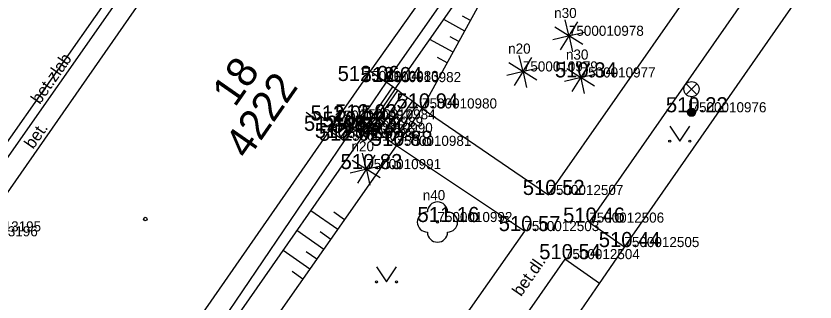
# Model space of a CAD drawing. Extents: x -669251 to -668549, y -1128351 to -1127698.
# Drawn here: x -668910.12 to -668870.46, y -1127865.22 to -1127851.02 of the extents above; entities that cross this region are included whole.
import ezdxf

# ---------------------------------------------------------------- set-up
doc = ezdxf.new("R2010")
doc.units = 0
for name, color, linetype in [('Vrstva 1', 7, 'Continuous'), ('Vrstva 10', 7, 'Continuous'), ('Vrstva 11', 7, 'Continuous'), ('Vrstva 14', 7, 'Continuous'), ('Vrstva 15', 7, 'Continuous'), ('Vrstva 2', 7, 'Continuous'), ('Vrstva 22', 7, 'Continuous'), ('Vrstva 24', 7, 'Continuous'), ('Vrstva 3', 7, 'Continuous'), ('Vrstva 33', 7, 'Continuous'), ('Vrstva 36', 7, 'Continuous'), ('Vrstva 40', 7, 'Continuous'), ('Vrstva 43', 7, 'Continuous'), ('Vrstva 44', 7, 'Continuous'), ('Vrstva 47', 7, 'Continuous'), ('Vrstva 5', 7, 'Continuous'), ('Vrstva 58', 7, 'Continuous'), ('Vrstva 6', 7, 'Continuous')]:
    doc.layers.add(name, color=color, linetype=linetype)

msp = doc.modelspace()

# ---------------------------------------------------------------- linework, layer by layer
at = {"layer": 'Vrstva 1'}
for p, q in [((-668882.677, -1127852.009), (-668882.677, -1127852.009)), ((-668884.962, -1127853.778), (-668884.962, -1127853.778)), ((-668892.859, -1127854.252), (-668892.859, -1127854.252)), ((-668891.745, -1127854.308), (-668891.745, -1127854.308)), ((-668882.094, -1127854.076), (-668882.094, -1127854.076)), ((-668889.962, -1127855.615), (-668889.962, -1127855.615)), ((-668876.589, -1127855.806), (-668876.589, -1127855.806)), ((-668894.225, -1127856.217), (-668894.225, -1127856.217)), ((-668893.009, -1127856.156), (-668893.009, -1127856.156)), ((-668894.554, -1127856.723), (-668894.554, -1127856.723)), ((-668893.631, -1127856.52), (-668893.631, -1127856.52)), ((-668894.015, -1127857.081), (-668894.015, -1127857.081)), ((-668893.154, -1127856.826), (-668893.154, -1127856.826)), ((-668893.808, -1127857.22), (-668893.808, -1127857.22)), ((-668891.237, -1127857.472), (-668891.237, -1127857.472)), ((-668892.737, -1127858.627), (-668892.737, -1127858.627)), ((-668883.69, -1127859.91), (-668883.69, -1127859.91)), ((-668889.2, -1127861.254), (-668889.2, -1127861.254)), ((-668881.667, -1127861.283), (-668881.667, -1127861.283)), ((-668884.887, -1127861.703), (-668884.887, -1127861.703)), ((-668879.919, -1127862.497), (-668879.919, -1127862.497)), ((-668882.875, -1127863.096), (-668882.875, -1127863.096))]:
    msp.add_line(p, q, dxfattribs=at)
at = {"layer": 'Vrstva 10'}
for p, q in [((-668883.69, -1127859.91), (-668874.225, -1127846.346)), ((-668881.667, -1127861.283), (-668872.238, -1127847.756)), ((-668891.745, -1127854.308), (-668887.822, -1127848.697)), ((-668891.293, -1127854.639), (-668887.343, -1127848.989)), ((-668879.919, -1127862.497), (-668870.46, -1127848.93)), ((-668913.476, -1127861.451), (-668905.08, -1127849.485)), ((-668913.109, -1127861.712), (-668904.712, -1127849.743)), ((-668891.293, -1127854.639), (-668892.563, -1127856.488)), ((-668889.962, -1127855.615), (-668883.69, -1127859.91)), ((-668901.53, -1127869.379), (-668892.563, -1127856.488)), ((-668901.884, -1127869.131), (-668893.808, -1127857.22)), ((-668884.887, -1127861.703), (-668891.237, -1127857.472)), ((-668879.919, -1127862.497), (-668881.667, -1127861.283)), ((-668884.887, -1127861.703), (-668893.875, -1127874.516)), ((-668881.164, -1127864.311), (-668879.919, -1127862.497)), ((-668882.875, -1127863.096), (-668891.824, -1127875.9)), ((-668881.164, -1127864.311), (-668882.875, -1127863.096)), ((-668889.953, -1127877.123), (-668881.164, -1127864.311))]:
    msp.add_line(p, q, dxfattribs=at)
at = {"layer": 'Vrstva 11'}
for p, q in [((-668892.516, -1127853.765), (-668891.745, -1127854.308)), ((-668891.745, -1127854.308), (-668893.009, -1127856.156)), ((-668891.414, -1127854.55), (-668891.745, -1127854.308)), ((-668892.683, -1127856.398), (-668891.414, -1127854.55)), ((-668892.442, -1127856.577), (-668891.172, -1127854.728)), ((-668891.293, -1127854.639), (-668891.414, -1127854.55)), ((-668891.172, -1127854.728), (-668891.293, -1127854.639)), ((-668890.93, -1127854.905), (-668891.172, -1127854.728)), ((-668892.201, -1127856.756), (-668890.93, -1127854.905)), ((-668891.96, -1127856.935), (-668890.688, -1127855.083)), ((-668890.688, -1127855.083), (-668890.93, -1127854.905)), ((-668890.446, -1127855.26), (-668890.688, -1127855.083)), ((-668891.719, -1127857.114), (-668890.446, -1127855.26)), ((-668891.478, -1127857.293), (-668890.204, -1127855.438)), ((-668891.237, -1127857.472), (-668889.962, -1127855.615)), ((-668890.204, -1127855.438), (-668890.446, -1127855.26)), ((-668889.962, -1127855.615), (-668890.204, -1127855.438)), ((-668893.808, -1127857.22), (-668893.009, -1127856.156)), ((-668893.009, -1127856.156), (-668892.683, -1127856.398)), ((-668892.683, -1127856.398), (-668892.563, -1127856.488)), ((-668894.554, -1127856.723), (-668894.015, -1127857.081)), ((-668892.563, -1127856.488), (-668892.442, -1127856.577)), ((-668892.442, -1127856.577), (-668892.201, -1127856.756)), ((-668892.201, -1127856.756), (-668891.96, -1127856.935)), ((-668894.015, -1127857.081), (-668893.808, -1127857.22)), ((-668891.96, -1127856.935), (-668891.719, -1127857.114)), ((-668891.719, -1127857.114), (-668891.478, -1127857.293)), ((-668891.478, -1127857.293), (-668891.237, -1127857.472))]:
    msp.add_line(p, q, dxfattribs=at)
at = {"layer": 'Vrstva 14'}
for p, q in [((-668889.962, -1127855.615), (-668886.276, -1127848.913)), ((-668900.226, -1127870.29), (-668891.237, -1127857.472))]:
    msp.add_line(p, q, dxfattribs=at)
at = {"layer": 'Vrstva 15'}
for p, q in [((-668887.848, -1127851.772), (-668888.889, -1127851.2)), ((-668887.559, -1127851.246), (-668887.953, -1127851.03)), ((-668888.137, -1127852.298), (-668888.576, -1127852.056)), ((-668888.427, -1127852.823), (-668889.58, -1127852.189)), ((-668888.716, -1127853.349), (-668889.2, -1127853.083)), ((-668894.153, -1127861.629), (-668895.488, -1127860.693)), ((-668893.808, -1127861.138), (-668894.343, -1127860.763)), ((-668894.842, -1127862.612), (-668896.173, -1127861.678)), ((-668894.497, -1127862.12), (-668895.03, -1127861.746)), ((-668895.531, -1127863.594), (-668896.858, -1127862.663)), ((-668895.186, -1127863.103), (-668895.718, -1127862.73)), ((-668895.875, -1127864.085), (-668896.405, -1127863.713))]:
    msp.add_line(p, q, dxfattribs=at)
at = {"layer": 'Vrstva 22'}
for p, q in [((-668882.685, -1127851.969), (-668882.857, -1127851.215)), ((-668882.711, -1127851.989), (-668883.367, -1127851.575)), ((-668882.243, -1127851.319), (-668882.657, -1127851.975)), ((-668883.471, -1127852.189), (-668882.717, -1127852.017)), ((-668882.697, -1127852.043), (-668883.111, -1127852.699)), ((-668882.669, -1127852.049), (-668882.497, -1127852.803)), ((-668881.987, -1127852.443), (-668882.643, -1127852.029)), ((-668882.637, -1127852.001), (-668881.883, -1127851.829)), ((-668884.97, -1127853.738), (-668885.142, -1127852.984)), ((-668884.528, -1127853.088), (-668884.942, -1127853.744)), ((-668884.996, -1127853.758), (-668885.652, -1127853.344)), ((-668884.922, -1127853.77), (-668884.168, -1127853.598)), ((-668882.128, -1127854.056), (-668882.784, -1127853.642)), ((-668882.102, -1127854.036), (-668882.274, -1127853.282)), ((-668881.66, -1127853.386), (-668882.074, -1127854.042)), ((-668885.756, -1127853.958), (-668885.002, -1127853.786)), ((-668884.982, -1127853.812), (-668885.396, -1127854.468)), ((-668884.954, -1127853.818), (-668884.782, -1127854.572)), ((-668884.272, -1127854.212), (-668884.928, -1127853.798)), ((-668882.054, -1127854.068), (-668881.3, -1127853.896)), ((-668882.888, -1127854.256), (-668882.134, -1127854.084)), ((-668882.114, -1127854.11), (-668882.528, -1127854.766)), ((-668882.086, -1127854.116), (-668881.914, -1127854.87)), ((-668881.404, -1127854.51), (-668882.06, -1127854.096)), ((-668892.745, -1127858.587), (-668892.917, -1127857.833)), ((-668892.303, -1127857.937), (-668892.717, -1127858.593)), ((-668892.771, -1127858.607), (-668893.427, -1127858.193)), ((-668893.531, -1127858.807), (-668892.777, -1127858.635)), ((-668892.757, -1127858.661), (-668893.171, -1127859.317)), ((-668892.729, -1127858.667), (-668892.557, -1127859.421)), ((-668892.047, -1127859.061), (-668892.703, -1127858.647)), ((-668892.697, -1127858.619), (-668891.943, -1127858.447))]:
    msp.add_line(p, q, dxfattribs=at)
for centre, radius in [((-668882.677, -1127852.009), 0.04), ((-668884.962, -1127853.778), 0.04), ((-668882.094, -1127854.076), 0.04), ((-668892.737, -1127858.627), 0.04), ((-668889.2, -1127861.254), 0.05)]:
    msp.add_circle(centre, radius, dxfattribs=at)
for centre, start, end in [((-668889.2, -1127860.754), 0, 180), ((-668889.7, -1127861.254), 90, 270), ((-668888.7, -1127861.254), 270, 90), ((-668889.2, -1127861.754), 180, 0)]:
    msp.add_arc(centre, 0.5, start, end, dxfattribs=at)
at = {"layer": 'Vrstva 24'}
for p, q in [((-668895.719, -1127855.806), (-668895.202, -1127856.16)), ((-668895.202, -1127856.16), (-668895.371, -1127855.742)), ((-668895.371, -1127855.742), (-668894.648, -1127856.236)), ((-668894.648, -1127856.236), (-668894.789, -1127856.007)), ((-668894.913, -1127856.188), (-668894.648, -1127856.236)), ((-668893.67, -1127856.578), (-668894.225, -1127856.217)), ((-668894.015, -1127857.081), (-668893.67, -1127856.578))]:
    msp.add_line(p, q, dxfattribs=at)
at = {"layer": 'Vrstva 33'}
for p, q in [((-668876.854, -1127854.391), (-668876.324, -1127854.921)), ((-668876.854, -1127854.921), (-668876.324, -1127854.391)), ((-668876.589, -1127855.806), (-668876.589, -1127855.031))]:
    msp.add_line(p, q, dxfattribs=at)
for centre, radius in [((-668876.589, -1127854.656), 0.375), ((-668876.589, -1127855.806), 0.2), ((-668876.589, -1127855.806), 0.18), ((-668876.589, -1127855.806), 0.16), ((-668876.589, -1127855.806), 0.14), ((-668876.589, -1127855.806), 0.12), ((-668876.589, -1127855.806), 0.1), ((-668876.589, -1127855.806), 0.08), ((-668876.589, -1127855.806), 0.06), ((-668876.589, -1127855.806), 0.04), ((-668876.589, -1127855.806), 0.02)]:
    msp.add_circle(centre, radius, dxfattribs=at)
at = {"layer": 'Vrstva 36'}
for p, q in [((-668877.673, -1127856.494), (-668877.173, -1127857.244)), ((-668877.173, -1127857.244), (-668876.673, -1127856.494)), ((-668892.232, -1127863.479), (-668891.732, -1127864.229)), ((-668891.732, -1127864.229), (-668891.232, -1127863.479))]:
    msp.add_line(p, q, dxfattribs=at)
for centre in [(-668877.673, -1127857.244), (-668876.673, -1127857.244), (-668892.232, -1127864.229), (-668891.232, -1127864.229)]:
    msp.add_circle(centre, 0.05, dxfattribs=at)
at = {"layer": 'Vrstva 5'}
for p, q in [((-668892.516, -1127853.765), (-668888.214, -1127847.662)), ((-668912.114, -1127862.052), (-668903.875, -1127850.202)), ((-668892.859, -1127854.252), (-668892.516, -1127853.765)), ((-668894.554, -1127856.723), (-668894.225, -1127856.217)), ((-668902.765, -1127868.518), (-668894.554, -1127856.723))]:
    msp.add_line(p, q, dxfattribs=at)
at = {"layer": 'Vrstva 58'}
msp.add_circle((-668903.701, -1127861.106), 0.0875, dxfattribs=at)
at = {"layer": 'Vrstva 6'}
msp.add_line((-668894.225, -1127856.217), (-668892.859, -1127854.252), dxfattribs=at)

# ---------------------------------------------------------------- texts
at = {"layer": 'Vrstva 2'}
for s, p in [('7500010978', (-668882.677, -1127852.009)), ('7500010979', (-668884.962, -1127853.778)), ('7500010977', (-668882.094, -1127854.076)), ('7500010983', (-668892.859, -1127854.252)), ('7500010982', (-668891.745, -1127854.308)), ('7500010980', (-668889.962, -1127855.615)), ('7500010976', (-668876.589, -1127855.806)), ('7500010987', (-668894.225, -1127856.217)), ('7500010989', (-668893.631, -1127856.52)), ('7500010984', (-668893.009, -1127856.156)), ('7500010986', (-668894.554, -1127856.723)), ('7500010990', (-668893.154, -1127856.826)), ('7500010988', (-668894.015, -1127857.081)), ('7500010985', (-668893.808, -1127857.22)), ('7500010981', (-668891.237, -1127857.472)), ('7500010991', (-668892.737, -1127858.627)), ('7500012507', (-668883.69, -1127859.91)), ('7500010992', (-668889.2, -1127861.254)), ('7500012506', (-668881.667, -1127861.283)), ('7500013196', (-668912.757, -1127861.963)), ('7500013195', (-668912.592, -1127861.719)), ('7500012503', (-668884.887, -1127861.703)), ('7500012505', (-668879.919, -1127862.497)), ('7500012504', (-668882.875, -1127863.096))]:
    msp.add_text(s, height=0.5, dxfattribs=at).set_placement(p)
at = {"layer": 'Vrstva 3'}
for s, p in [('512.06 ', (-668894.155, -1127854.252)), ('512.04 ', (-668893.019, -1127854.308)), ('510.34 ', (-668883.368, -1127854.076)), ('510.94 ', (-668891.238, -1127855.615)), ('510.22 ', (-668877.863, -1127855.806)), ('512.05 ', (-668895.499, -1127856.217)), ('512.03 ', (-668894.283, -1127856.156)), ('512.05 ', (-668895.828, -1127856.723)), ('510.53 ', (-668894.905, -1127856.52)), ('510.54 ', (-668895.289, -1127857.081)), ('510.43 ', (-668894.428, -1127856.826)), ('512.02 ', (-668895.082, -1127857.22)), ('510.88 ', (-668892.511, -1127857.472)), ('510.83 ', (-668894.011, -1127858.627)), ('510.52 ', (-668884.964, -1127859.91)), ('511.16 ', (-668890.192, -1127861.254)), ('510.46 ', (-668882.963, -1127861.283)), ('510.57 ', (-668886.161, -1127861.703)), ('510.44 ', (-668881.193, -1127862.497)), ('510.54 ', (-668884.149, -1127863.096))]:
    msp.add_text(s, height=0.75, dxfattribs=at).set_placement(p)
at = {"layer": 'Vrstva 40'}
for s, rotation, p in [('bet.zlab', 54.9464, (-668908.939, -1127855.445)), ('bet.', 55.1892, (-668909.266, -1127857.669)), ('bet.dl.', 55.0494, (-668885.05, -1127864.986))]:
    msp.add_text(s, height=0.6, rotation=rotation, dxfattribs=at).set_placement(p)
at = {"layer": 'Vrstva 43'}
msp.add_text('4222', height=1.5, rotation=55.157, dxfattribs=at).set_placement((-668898.625, -1127858.196))
at = {"layer": 'Vrstva 44'}
msp.add_text('18', height=1.5, rotation=55.157, dxfattribs=at).set_placement((-668899.254, -1127855.599))
at = {"layer": 'Vrstva 47'}
for s, height, p in [('n30', 0.5, (-668883.407, -1127851.123)), ('n20', 0.5, (-668885.692, -1127852.892)), ('n30', 0.5, (-668882.824, -1127853.19)), ('n20', 0.5, (-668893.467, -1127857.741)), ('n40', 0.499, (-668889.929, -1127860.168))]:
    msp.add_text(s, height=height, dxfattribs=at).set_placement(p)

doc.saveas('drawing.dxf')
